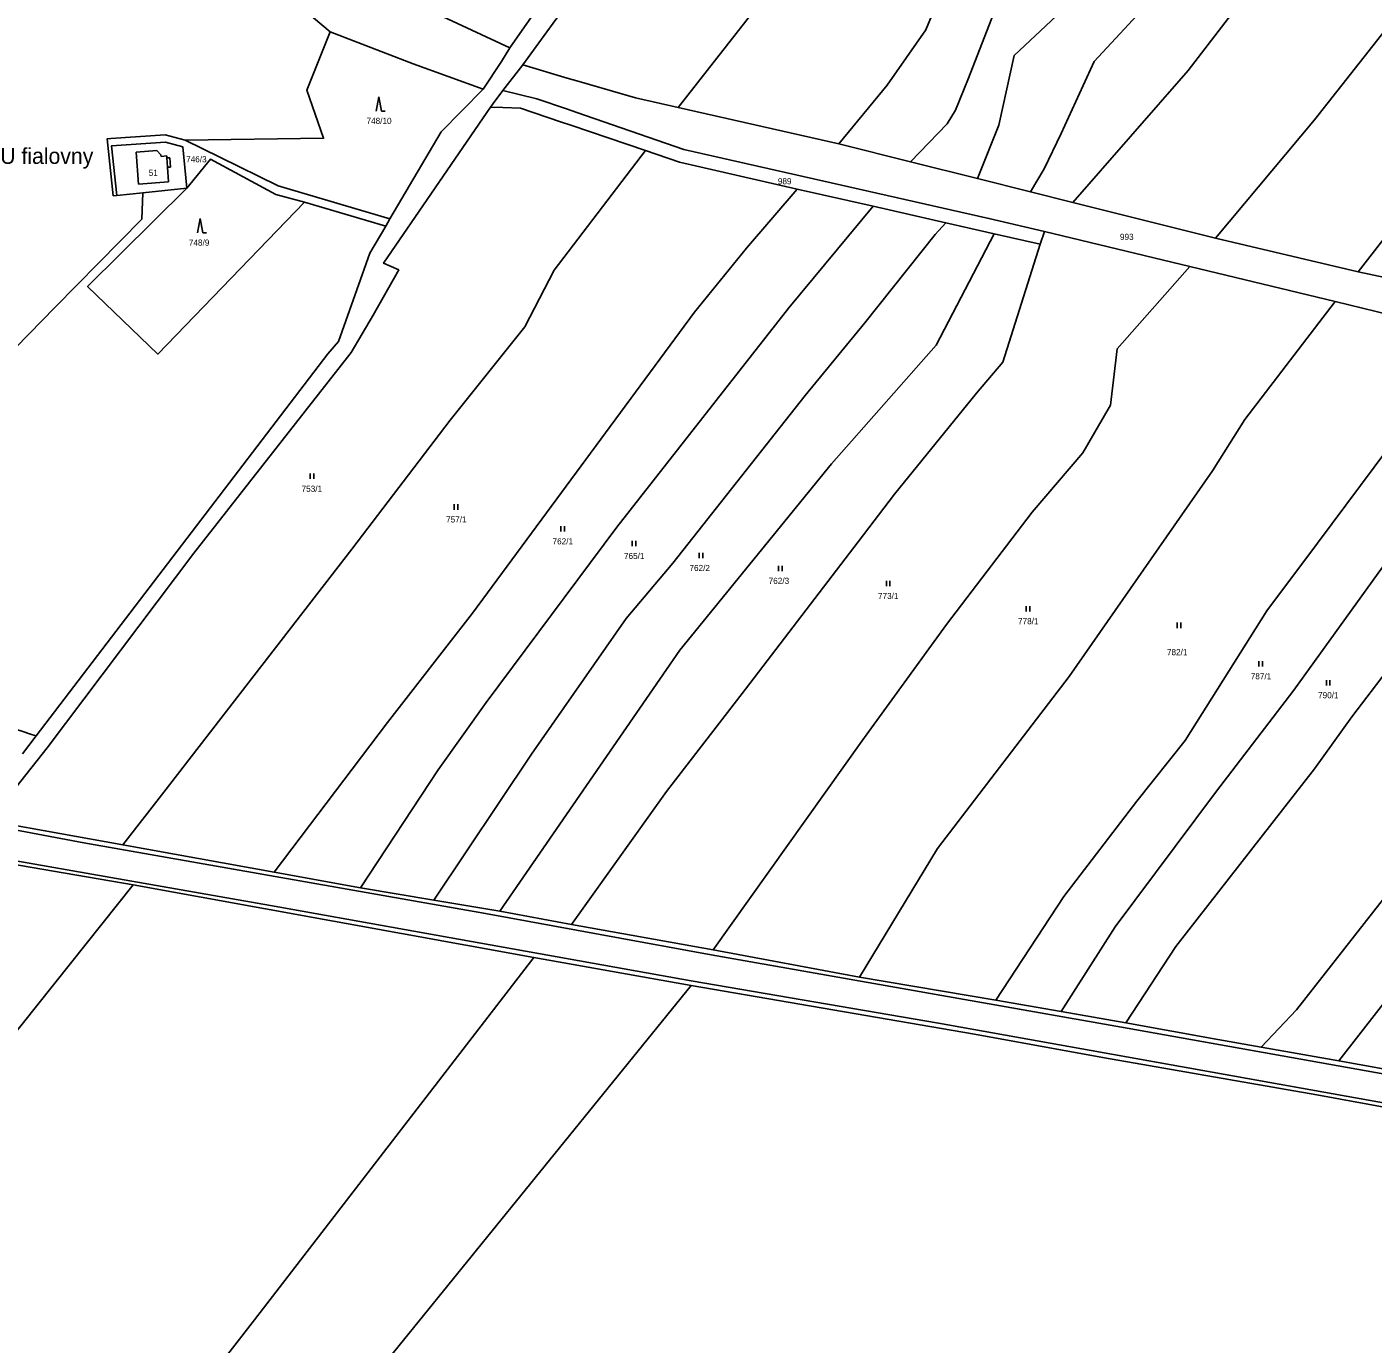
# Model space of a CAD drawing. Extents: x -751333 to -746055, y -1133395 to -1129777.
# Drawn here: x -748476.3 to -748102.9, y -1131870.5 to -1131505.2 of the extents above; entities that cross this region are included whole.
import ezdxf

# ---------------------------------------------------------------- set-up
doc = ezdxf.new("R2010")
doc.units = 0
for name, color, linetype in [('Hranice parcel', 7, 'Continuous'), ('Parcelní čísla', 7, 'Continuous'), ('Pop  PČ popisy', 7, 'Continuous'), ('Vnitřní kresba', 7, 'Continuous'), ('Značky kultur', 7, 'Continuous')]:
    doc.layers.add(name, color=color, linetype=linetype)

msp = doc.modelspace()

# ---------------------------------------------------------------- linework, layer by layer
at = {"layer": 'Hranice parcel'}
for p, q in [((-748320.12, -1131479.22), (-748342.35, -1131510.98)), ((-748342.35, -1131510.98), (-748385.83, -1131490.72)), ((-748344.25, -1131522.86), (-748338.7, -1131515.67)), ((-748251.1, -1131537.65), (-748295.63, -1131527.57)), ((-748432.47, -1131536.6), (-748437.99, -1131535.12)), ((-748251.1, -1131537.65), (-748231.2, -1131542.62)), ((-748212.64, -1131547.25), (-748231.2, -1131542.62)), ((-748444.16, -1131551.22), (-748431.92, -1131549.94)), ((-748241.52, -1131554.96), (-748262.6, -1131550.16)), ((-748197.93, -1131550.92), (-748212.64, -1131547.25)), ((-748452.39, -1131552.07), (-748451.39, -1131551.97)), ((-748451.39, -1131551.97), (-748444.16, -1131551.22)), ((-748399.33, -1131553.79), (-748376.75, -1131560.47)), ((-748186.16, -1131553.86), (-748197.93, -1131550.92)), ((-748146.55, -1131563.75), (-748186.16, -1131553.86)), ((-748241.52, -1131554.96), (-748221.35, -1131559.55)), ((-748376.75, -1131560.47), (-748375.6, -1131558.41)), ((-748221.35, -1131559.55), (-748207.96, -1131562.6)), ((-748207.96, -1131562.6), (-748195.25, -1131565.49)), ((-748195.25, -1131565.49), (-748194.06, -1131561.97)), ((-748194.06, -1131561.97), (-748153.68, -1131571.69)), ((-748107.04, -1131573.14), (-748146.55, -1131563.75)), ((-748153.68, -1131571.69), (-748113.41, -1131581.39)), ((-748113.41, -1131581.39), (-748073.44, -1131591)), ((-748477.57, -1131706.86), (-748473.73, -1131701.81)), ((-748449.71, -1131732.09), (-748486.77, -1131725.36)), ((-748407.72, -1131739.65), (-748449.71, -1131732.09)), ((-748407.72, -1131739.65), (-748383.77, -1131744.02)), ((-748335.68, -1131763.31), (-748446.88, -1131743.14)), ((-748363.42, -1131747.42), (-748383.77, -1131744.02)), ((-748345.13, -1131750.42), (-748363.42, -1131747.42)), ((-748325.27, -1131754.18), (-748345.13, -1131750.42)), ((-748285.94, -1131761.16), (-748325.27, -1131754.18)), ((-748245.31, -1131768.76), (-748285.94, -1131761.16)), ((-748292.03, -1131771.09), (-748335.68, -1131763.31)), ((-748207.51, -1131775.13), (-748245.31, -1131768.76)), ((-748189.42, -1131778.25), (-748207.51, -1131775.13)), ((-748171.43, -1131781.47), (-748189.42, -1131778.25)), ((-748112.41, -1131792), (-748133.95, -1131788.17)), ((-748090.69, -1131795.87), (-748112.41, -1131792))]:
    msp.add_line(p, q, dxfattribs=at)
for points in [[(-748392.16, -1131506.55), (-748408.97, -1131492.45), (-748455.93, -1131466.65), (-748484.5, -1131445.39), (-748502.39, -1131429.25), (-748511.24, -1131427.32), (-748518.9, -1131418.34), (-748522.93, -1131412.38), (-748534.82, -1131400.07), (-748560.04, -1131371.4), (-748567.63, -1131359.17), (-748618.14, -1131307.59), (-748670.88, -1131247.89), (-748697.81, -1131219.81), (-748711.66, -1131216.37), (-748756.69, -1131177.5), (-748810.83, -1131139.93), (-748841.05, -1131093.93), (-748849.27, -1131076.16), (-748875.35, -1131042.49), (-748884.41, -1131032.45), (-748897.97, -1131021.96), (-748903.36, -1131031.29)], [(-748338.7, -1131515.67), (-748332.06, -1131506.58), (-748330.29, -1131504.16), (-748281.35, -1131437.18), (-748259.4, -1131407.56), (-748238.32, -1131382.13), (-748230.61, -1131373.58), (-748194.83, -1131320.25), (-748186.88, -1131309.09), (-748150.94, -1131258.6), (-748147.3, -1131255.64), (-748127.32, -1131239.4)], [(-748295.63, -1131527.57), (-748247.36, -1131465.87), (-748231.37, -1131444.65), (-748232.47, -1131443.55), (-748145.12, -1131333.41), (-748128.85, -1131299.01)], [(-748109.16, -1131342.95), (-748123.81, -1131361.87), (-748135.1, -1131380.02), (-748179.46, -1131434.11), (-748212.49, -1131471.24), (-748226.97, -1131506.03), (-748237.67, -1131521.37), (-748251.1, -1131537.65)], [(-748231.2, -1131542.62), (-748221.01, -1131532.05), (-748218.72, -1131528.27), (-748215.12, -1131519.4), (-748202.99, -1131488.16), (-748179.78, -1131463.77), (-748164.25, -1131446.94), (-748144.37, -1131423.16), (-748124.36, -1131396.05), (-748102.88, -1131363.67)], [(-748212.64, -1131547.25), (-748206.7, -1131532.49), (-748202.43, -1131513.11), (-748190.71, -1131502.08), (-748160.01, -1131465.57), (-748146.07, -1131449.57), (-748120.34, -1131419.08), (-748097.84, -1131383.08)], [(-748197.93, -1131550.92), (-748194.08, -1131544.52), (-748189.38, -1131534.76), (-748180.26, -1131514.82), (-748142.13, -1131473.68), (-748122.88, -1131448.54), (-748104.89, -1131424.02), (-748091.49, -1131402.75)], [(-748186.16, -1131553.86), (-748154.21, -1131517.27), (-748125.78, -1131480.26), (-748093.8, -1131442.91), (-748083.86, -1131424.07)], [(-748146.55, -1131563.75), (-748119.12, -1131530.98), (-748066.79, -1131464.53)], [(-748432.47, -1131536.6), (-748394.02, -1131536.07), (-748398.68, -1131522.74), (-748392.16, -1131506.55)], [(-748392.16, -1131506.55), (-748369.17, -1131515.42), (-748349.71, -1131522.42)], [(-748107.04, -1131573.14), (-748088.51, -1131549.4), (-748050.59, -1131506.3)], [(-748342.35, -1131510.98), (-748344.69, -1131514.82), (-748349.71, -1131522.42)], [(-748295.63, -1131527.57), (-748307.46, -1131524.9), (-748320.25, -1131521.2), (-748323.16, -1131520.36), (-748326.43, -1131519.41), (-748338.7, -1131515.67)], [(-748349.71, -1131522.42), (-748361.37, -1131534.34), (-748375.6, -1131558.41)], [(-748347.75, -1131527.48), (-748346.96, -1131526.43), (-748344.25, -1131522.86)], [(-748194.06, -1131561.97), (-748209.42, -1131558.33), (-748294.08, -1131539.17), (-748323.79, -1131528.94), (-748326.65, -1131527.96), (-748334.86, -1131525.13), (-748344.25, -1131522.86)], [(-748486.77, -1131725.36), (-748470.71, -1131705.15), (-748430, -1131651.16), (-748386.35, -1131595.53), (-748380.27, -1131585.17), (-748373.15, -1131572.6), (-748377.39, -1131570.73), (-748348.74, -1131528.93), (-748347.75, -1131527.48)], [(-748347.75, -1131527.48), (-748344.25, -1131527.58), (-748339.37, -1131527.72), (-748328.27, -1131531.5), (-748325.41, -1131532.47), (-748304.71, -1131539.52)], [(-748437.99, -1131535.12), (-748453.04, -1131536.11), (-748454.05, -1131536.22), (-748452.39, -1131552.07)], [(-748431.92, -1131549.94), (-748433.11, -1131538.5), (-748437.84, -1131537.2), (-748452.83, -1131538.17), (-748451.39, -1131551.97)], [(-748375.6, -1131558.41), (-748406.59, -1131549.32), (-748422.84, -1131541.28), (-748432.47, -1131536.6)], [(-748449.71, -1131732.09), (-748438.32, -1131717.49), (-748386.17, -1131650.03), (-748358.92, -1131614.29), (-748338.21, -1131588.38), (-748330.01, -1131572.7), (-748304.71, -1131539.52)], [(-748431.92, -1131549.94), (-748425.42, -1131541.92), (-748407.25, -1131551.64), (-748399.33, -1131553.79)], [(-748304.71, -1131539.52), (-748295.27, -1131542.73), (-748262.6, -1131550.16)], [(-748431.92, -1131549.94), (-748459.5, -1131577.18), (-748440.01, -1131595.93), (-748399.33, -1131553.79)], [(-748262.6, -1131550.16), (-748276.68, -1131566.53), (-748291.14, -1131584.32), (-748352.73, -1131667.79), (-748376.31, -1131698.17), (-748407.72, -1131739.65)], [(-748595.3, -1131671.34), (-748594.1, -1131624.89), (-748505.15, -1131620.41), (-748468.46, -1131582.9), (-748444.47, -1131558.56), (-748444.16, -1131551.22)], [(-748383.77, -1131744.02), (-748362.25, -1131711.28), (-748348.88, -1131692.58), (-748312.63, -1131643.99), (-748264.94, -1131583.09), (-748241.52, -1131554.96)], [(-748376.75, -1131560.47), (-748381.17, -1131567.99), (-748384.76, -1131578.08), (-748389.85, -1131592.41), (-748392.88, -1131595.87), (-748473.73, -1131701.81)], [(-748221.35, -1131559.55), (-748224.32, -1131562.77), (-748243.89, -1131587.32), (-748260.4, -1131607.42), (-748297.09, -1131653.9), (-748310.1, -1131669.29), (-748336.31, -1131706.87), (-748363.42, -1131747.42)], [(-748345.13, -1131750.42), (-748295.17, -1131678.04), (-748253.07, -1131626.4), (-748224.07, -1131593.46), (-748207.96, -1131562.6)], [(-748325.27, -1131754.18), (-748298.92, -1131717.28), (-748277, -1131688.88), (-748245.73, -1131647.99), (-748235.68, -1131634.79), (-748212.89, -1131606.75), (-748205.55, -1131598.18), (-748195.25, -1131565.49)], [(-748285.94, -1131761.16), (-748244.67, -1131703.3), (-748221.18, -1131670.97), (-748197.42, -1131639.78), (-748183.36, -1131623.35), (-748175.75, -1131610.07), (-748173.83, -1131594.48), (-748153.68, -1131571.69)], [(-748067.18, -1131582.32), (-748083.49, -1131578.1), (-748107.04, -1131573.14)], [(-748245.31, -1131768.76), (-748223.72, -1131733.12), (-748187.2, -1131685.33), (-748147.37, -1131628.37), (-748138.47, -1131614.13), (-748113.41, -1131581.39)], [(-748207.51, -1131775.13), (-748188.65, -1131746.41), (-748168.43, -1131719.93), (-748155.02, -1131703.11), (-748132.31, -1131667.15), (-748118.25, -1131648.37), (-748098.51, -1131621.85), (-748082.22, -1131602.16), (-748073.44, -1131591)], [(-748189.42, -1131778.25), (-748174.41, -1131754.8), (-748146.56, -1131717.59), (-748124.81, -1131689.2), (-748094.48, -1131647.14), (-748068.06, -1131612.64), (-748056.72, -1131598.66)], [(-748171.43, -1131781.47), (-748157.61, -1131760.26), (-748119.14, -1131710.95), (-748108.79, -1131696.59), (-748068.88, -1131644.35), (-748037.55, -1131603.66)], [(-748133.95, -1131788.17), (-748124.07, -1131777.87), (-748094.64, -1131740.22), (-748069.05, -1131705.81), (-748011.59, -1131624.57)], [(-748006.29, -1131648.59), (-748036.71, -1131691.7), (-748068.58, -1131735.81), (-748112.41, -1131792)], [(-748473.73, -1131701.81), (-748475.01, -1131701.42), (-748477.99, -1131700.43), (-748536.85, -1131682.69), (-748595.3, -1131671.34)], [(-748446.88, -1131743.14), (-748491.15, -1131735.61), (-748494.16, -1131735.1), (-748495.25, -1131734.91)], [(-748595.25, -1131929.58), (-748577.39, -1131907.29), (-748530.22, -1131847.71), (-748446.88, -1131743.14)], [(-748335.68, -1131763.31), (-748413.16, -1131863.8), (-748483.93, -1131954.75), (-748519.98, -1132001.85), (-748494.64, -1132021.23), (-748393.32, -1131895.86), (-748292.03, -1131771.09)], [(-747873.81, -1131844.78), (-747910.86, -1131838.67), (-747949.78, -1131831.83), (-747967.09, -1131828.83), (-748097.72, -1131805.16), (-748118.43, -1131801.42), (-748177.37, -1131791.12), (-748213.42, -1131784.62), (-748292.03, -1131771.09)], [(-748133.95, -1131788.17), (-748145.89, -1131786.04), (-748171.43, -1131781.47)]]:
    msp.add_lwpolyline(points, dxfattribs=at)
at = {"layer": 'Vnitřní kresba'}
for p, q in [((-748446.02, -1131539.95), (-748440.32, -1131539.47)), ((-748446.02, -1131539.95), (-748445.36, -1131548.79)), ((-748439.13, -1131540.67), (-748440.32, -1131539.47)), ((-748439.09, -1131541.12), (-748439.13, -1131540.67)), ((-748437.55, -1131541), (-748439.09, -1131541.12)), ((-748437.51, -1131541.55), (-748437.55, -1131541)), ((-748436.66, -1131541.49), (-748437.51, -1131541.55)), ((-748437.51, -1131541.55), (-748437.31, -1131544.13)), ((-748436.47, -1131544.07), (-748436.66, -1131541.49)), ((-748437.31, -1131544.13), (-748436.47, -1131544.07)), ((-748437.01, -1131548.16), (-748437.31, -1131544.13)), ((-748437.01, -1131548.16), (-748445.36, -1131548.79)), ((-748460.54, -1131731.48), (-748487.83, -1131726.39)), ((-748349.14, -1131751.08), (-748460.54, -1131731.48)), ((-748408.71, -1131748.93), (-748490.74, -1131734.47)), ((-748292.01, -1131769.8), (-748408.71, -1131748.93)), ((-748286.51, -1131762.56), (-748349.14, -1131751.08)), ((-748171.11, -1131782.91), (-748286.51, -1131762.56)), ((-748223.47, -1131781.55), (-748292.01, -1131769.8)), ((-748095.39, -1131804.42), (-748223.47, -1131781.55)), ((-748097, -1131796.09), (-748171.11, -1131782.91))]:
    msp.add_line(p, q, dxfattribs=at)
at = {"layer": 'Značky kultur'}
for p, q in [((-748378.67, -1131524.56), (-748379.42, -1131528.56)), ((-748377.92, -1131528.56), (-748378.67, -1131524.56)), ((-748377.92, -1131528.56), (-748376.924, -1131528.56)), ((-748428.28, -1131558.32), (-748429.03, -1131562.32)), ((-748427.53, -1131562.32), (-748428.28, -1131558.32)), ((-748427.53, -1131562.32), (-748426.534, -1131562.32)), ((-748397.721, -1131630.59), (-748397.721, -1131629.09)), ((-748396.72, -1131630.59), (-748396.72, -1131629.09)), ((-748357.761, -1131639.1), (-748357.761, -1131637.6)), ((-748356.76, -1131639.1), (-748356.76, -1131637.6)), ((-748328.171, -1131645.18), (-748328.171, -1131643.68)), ((-748327.17, -1131645.18), (-748327.17, -1131643.68)), ((-748308.371, -1131649.24), (-748308.371, -1131647.74)), ((-748307.37, -1131649.24), (-748307.37, -1131647.74)), ((-748289.801, -1131652.57), (-748289.801, -1131651.07)), ((-748288.8, -1131652.57), (-748288.8, -1131651.07)), ((-748267.821, -1131656.14), (-748267.821, -1131654.64)), ((-748266.82, -1131656.14), (-748266.82, -1131654.64)), ((-748237.891, -1131660.34), (-748237.891, -1131658.84)), ((-748236.89, -1131660.34), (-748236.89, -1131658.84)), ((-748199.101, -1131667.33), (-748199.101, -1131665.83)), ((-748198.1, -1131667.33), (-748198.1, -1131665.83)), ((-748157.211, -1131671.92), (-748157.211, -1131670.42)), ((-748156.21, -1131671.92), (-748156.21, -1131670.42)), ((-748134.531, -1131682.61), (-748134.531, -1131681.11)), ((-748133.53, -1131682.61), (-748133.53, -1131681.11)), ((-748115.831, -1131687.86), (-748115.831, -1131686.36)), ((-748114.83, -1131687.86), (-748114.83, -1131686.36))]:
    msp.add_line(p, q, dxfattribs=at)

# ---------------------------------------------------------------- texts
at = {"layer": 'Parcelní čísla'}
for s, p in [('748/10', (-748382.11, -1131532.11)), ('746/3', (-748432.16, -1131542.76)), ('51', (-748442.55, -1131546.53)), ('989', (-748268, -1131548.85)), ('748/9', (-748431.4, -1131565.87)), ('993', (-748173.09, -1131564.28)), ('753/1', (-748400.12, -1131634.14)), ('757/1', (-748360.04, -1131642.65)), ('762/1', (-748330.51, -1131648.73)), ('765/1', (-748310.69, -1131652.79)), ('762/2', (-748292.52, -1131656.12)), ('762/3', (-748270.55, -1131659.69)), ('773/1', (-748240.21, -1131663.89)), ('778/1', (-748201.37, -1131670.88)), ('782/1', (-748160.05, -1131679.46)), ('787/1', (-748136.8, -1131686.16)), ('790/1', (-748118.13, -1131691.41))]:
    msp.add_text(s, height=1.7, dxfattribs=at).set_placement(p)
at = {"layer": 'Pop  PČ popisy'}
msp.add_text('U fialovny', height=4.4, dxfattribs=at).set_placement((-748483.73, -1131543.19))

doc.saveas('drawing.dxf')
